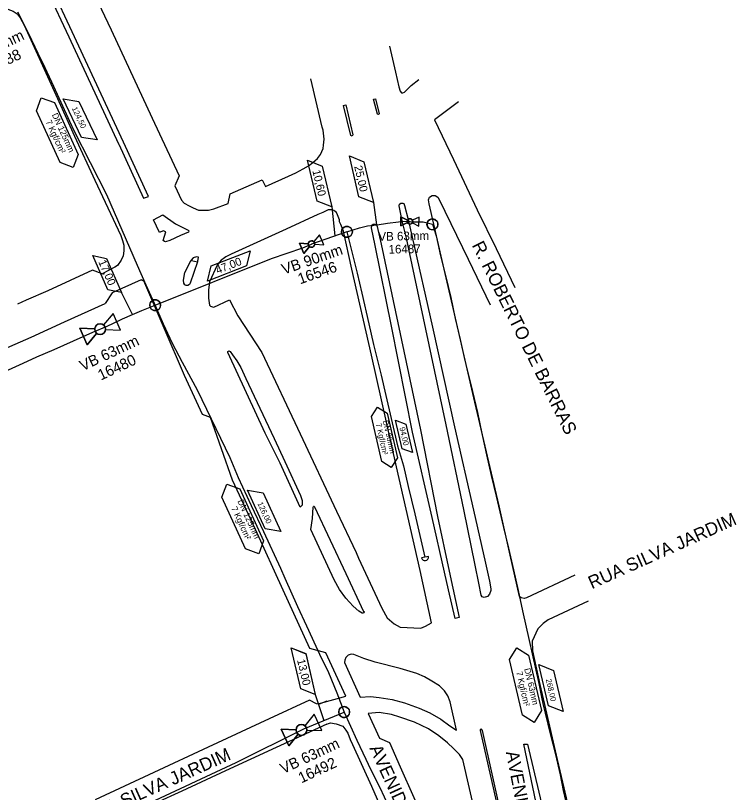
# Model space of a CAD drawing. Extents: x 656692 to 673945, y 7585994 to 7599066.
# Drawn here: x 669589.7 to 669990.1, y 7595459.1 to 7595890.6 of the extents above; entities that cross this region are included whole.
import ezdxf

# ---------------------------------------------------------------- set-up
doc = ezdxf.new("R2010")
doc.units = 0
for name, color, linetype in [('LOGRADOURO', 7, 'Continuous'), ('LOGRADOURO_TEXTO', 7, 'Continuous'), ('SIMBOLO', 7, 'Continuous'), ('TEXTO', 7, 'Continuous'), ('TUBO_PEAD_GN_125', 7, 'Continuous'), ('TUBO_PEAD_GN_63', 7, 'Continuous'), ('TUBO_PEAD_GN_90', 7, 'Continuous'), ('VALVULA_PEAD_63', 7, 'Continuous'), ('VALVULA_PEAD_90', 7, 'Continuous')]:
    doc.layers.add(name, color=color, linetype=linetype)

# ---------------------------------------------------------------- blocks, each defined once
blk = doc.blocks.new('VALVULA_PEAD_DN_17')
for points in [[(-0.0374, 0.0187), (-0.1395, 0.0698), (-0.1395, -0.0698), (-0.0374, -0.0187)], [(-0.0374, -0.0187), (-0.1395, -0.0698), (-0.1395, 0.0698), (-0.0374, 0.0187)], [(0.0374, -0.0187), (0.1395, -0.0698), (0.1395, 0.0698), (0.0374, 0.0187)], [(0.0374, -0.0187), (0.1395, -0.0698), (0.1395, 0.0698), (0.0374, 0.0187)]]:
    blk.add_lwpolyline(points)
blk.add_circle((0, 0), 0.0419)
for start, end in [(90, 270), (153.43495, 206.56505), (270, 90), (333.43495, 26.56505)]:
    blk.add_arc((0, 0), 0.0419, start, end)
blk = doc.blocks.new('VALVULA_PEAD_DN_16')
at = {"layer": 'VALVULA_PEAD_63'}
for points in [[(-0.0374, 0.0187), (-0.1395, 0.0698), (-0.1395, -0.0698), (-0.0374, -0.0187)], [(-0.0374, -0.0187), (-0.1395, -0.0698), (-0.1395, 0.0698), (-0.0374, 0.0187)], [(0.0374, -0.0187), (0.1395, -0.0698), (0.1395, 0.0698), (0.0374, 0.0187)], [(0.0374, -0.0187), (0.1395, -0.0698), (0.1395, 0.0698), (0.0374, 0.0187)]]:
    blk.add_lwpolyline(points, dxfattribs=at)
blk.add_circle((0, 0), 0.0419, dxfattribs=at)
for start, end in [(90, 270), (153.43495, 206.56505), (270, 90), (333.43495, 26.56505)]:
    blk.add_arc((0, 0), 0.0419, start, end, dxfattribs=at)
blk = doc.blocks.new('INTERLIGACAO_9')
at = {"layer": 'SIMBOLO'}
blk.add_circle((0, 0), 4.19, dxfattribs=at)
for start, end in [(0, 180), (180, 0)]:
    blk.add_arc((0, 0), 4.19, start, end, dxfattribs=at)

msp = doc.modelspace()

# ---------------------------------------------------------------- linework, layer by layer
at = {"layer": 'LOGRADOURO'}
for points in [[(669626.5, 7595917.1), (669642.76, 7595882.69), (669665.64, 7595833.62), (669680.49, 7595801.6), (669678.22, 7595796.05), (669681.86, 7595788.09), (669683.31, 7595786.42), (669686.12, 7595784.82), (669688.31, 7595783.67), (669691.24, 7595782.53), (669693.42, 7595782.38), (669696.76, 7595782.38), (669699.88, 7595783.14), (669707.82, 7595786.21), (669708.87, 7595791.5), (669726.73, 7595799.31), (669728.46, 7595795.59), (669741.37, 7595801.35), (669745.32, 7595803.18), (669749.49, 7595805.46), (669752.32, 7595807.01), (669754.83, 7595808.9), (669757.44, 7595811.23), (669759.07, 7595813.43), (669760.45, 7595816.65), (669760.81, 7595818.51), (669761.05, 7595821.97), (669760.86, 7595823.57), (669760.47, 7595826.84), (669760.05, 7595828.63), (669753.74, 7595855.33)], [(669553.79, 7595882.06), (669580.42, 7595893.61), (669582.82, 7595894.1), (669585.35, 7595894.02), (669588.34, 7595892.98), (669590.53, 7595891.47), (669592.25, 7595889.23), (669594.49, 7595885.22), (669611.97, 7595846.58), (669622.46, 7595823.54), (669633.74, 7595799.1), (669648.11, 7595768.42), (669649.11, 7595765.62), (669649.81, 7595762.99), (669649.9, 7595759.85), (669649.5, 7595757.16), (669648.42, 7595754.65), (669646.35, 7595751.78), (669644.89, 7595750.78), (669637.86, 7595747.18), (669632.34, 7595749.1), (669607.54, 7595737.68)], [(669797.31, 7595873.61), (669800.8, 7595859.03), (669802.64, 7595850.96), (669803.28, 7595848.52), (669804.09, 7595847.63), (669804.88, 7595847.67), (669805.68, 7595848.03), (669809.42, 7595851.65), (669813.63, 7595855.12)], [(669835.77, 7595842.7), (669822.33, 7595832.65), (669832.9, 7595810.63), (669846.14, 7595782.71), (669856.67, 7595761.12), (669867.05, 7595739.51)], [(669900.31, 7595579.73), (669873.55, 7595567.21), (669872.18, 7595566.8), (669870.6, 7595567.14), (669869.5, 7595567.96), (669864.44, 7595590.79), (669858.28, 7595618.33), (669844.74, 7595675.82), (669835.11, 7595717.66), (669826.58, 7595754.43), (669819.36, 7595786.07), (669819.1, 7595788.19), (669819.64, 7595789.73), (669821.1, 7595790.67), (669822.73, 7595790.7), (669824.28, 7595789.64), (669825.01, 7595788.42), (669841.04, 7595755.28), (669853.38, 7595729.85)], [(669690.68, 7595753.82), (669686.75, 7595741.96), (669686.28, 7595741.15), (669685.45, 7595740.68), (669684.49, 7595740.56), (669683.69, 7595741.09), (669683.23, 7595741.98), (669682.96, 7595743.57), (669683.71, 7595747.78), (669687.28, 7595754.63), (669687.33, 7595754.58), (669690.68, 7595753.82), (669691.15, 7595755.11), (669691.25, 7595756.29), (669690.21, 7595756.56), (669688.42, 7595756.04), (669687.28, 7595754.63)], [(669757.69, 7595508.22), (669773.04, 7595512.59), (669761.95, 7595536.58), (669753.17, 7595539.09), (669738.38, 7595571.37), (669722.99, 7595605.03), (669710.1, 7595632.55), (669697.93, 7595667.32), (669693.56, 7595668.97), (669683.56, 7595690.6), (669660.88, 7595743.27), (669659.5, 7595743.83), (669643.32, 7595736.53), (669639.47, 7595730.71)], [(669659.5, 7595743.83), (669660.88, 7595743.28), (669664.83, 7595734.55)], [(669607.54, 7595737.68), (669595.57, 7595732.41), (669590.79, 7595730.26)], [(669573.09, 7595444.9), (669568.9, 7595463.16), (669562.37, 7595492.14), (669557.21, 7595514.33), (669553.14, 7595532.15), (669552.15, 7595536.82), (669545.25, 7595567.44), (669541.15, 7595585.45), (669533.84, 7595617.5), (669528.2, 7595642.69), (669523.3, 7595663.52), (669518.93, 7595664.92), (669517.03, 7595673.72), (669516.85, 7595676.41), (669517.26, 7595678.43), (669518.23, 7595680.04), (669519, 7595680.94), (669535.25, 7595688.41), (669542.22, 7595686.89), (669552.84, 7595691.94), (669583.46, 7595705.45), (669598.26, 7595711.96), (669616.78, 7595720.51), (669639.47, 7595730.71)], [(669907.78, 7595565.23), (669885.57, 7595555.02), (669882.73, 7595552.97), (669879.76, 7595549.96), (669876.58, 7595543.18), (669876.74, 7595537.65), (669880.81, 7595518.96), (669884, 7595505.49), (669890.56, 7595477.33), (669899.18, 7595440.34), (669919.49, 7595352.19), (669922.93, 7595337.43), (669927.48, 7595318.19), (669928.82, 7595313.85), (669931.88, 7595309.53), (669937, 7595308.26), (669942.3, 7595308.75), (669944.73, 7595309.52), (669968, 7595320.27)], [(669762.51, 7595509.83), (669758.3, 7595508.19), (669756.76, 7595508.28), (669753, 7595510.3), (669730.61, 7595500.03), (669696.68, 7595484.27), (669666.46, 7595470.15), (669633.85, 7595455.06)], [(669845.58, 7595445.09), (669838.19, 7595477.44), (669836.22, 7595480.25), (669832.95, 7595483.5), (669829.58, 7595486.58), (669824.74, 7595490.52), (669818.97, 7595494.48), (669811.3, 7595498.16), (669803.15, 7595500.96), (669798.42, 7595502.35), (669791.71, 7595503.41), (669785.47, 7595502.94), (669791.84, 7595489.29), (669797.31, 7595486.82), (669803.34, 7595473.27), (669818.44, 7595439.25)], [(669652.94, 7595446.6), (669682.16, 7595460.01), (669706.4, 7595471.33), (669762.77, 7595497.12)], [(669761.52, 7595496.64), (669764.7, 7595497.67), (669767.78, 7595497.25), (669771.48, 7595495.84), (669773.04, 7595493.76), (669774.32, 7595491.97), (669775.54, 7595488.56), (669776.89, 7595485.73), (669787.41, 7595462.62), (669799.64, 7595434.65)], [(669860.86, 7595440.34), (669848.96, 7595493.48), (669848.48, 7595494.15), (669847.74, 7595493.99), (669847.68, 7595493.52), (669859.85, 7595440.29)], [(669884.68, 7595425.72), (669871.99, 7595485.94), (669874.02, 7595485.91), (669888.13, 7595426.35)]]:
    msp.add_lwpolyline(points, dxfattribs=at)
for points in [[(669607.45, 7595905.13), (669607.4, 7595904.23), (669607.57, 7595903.69), (669619.3, 7595878.82), (669646.8, 7595819.29), (669647.05, 7595819.15), (669660.73, 7595789.07), (669663.51, 7595790.14), (669649.55, 7595820.32), (669621.14, 7595881.57), (669610.2, 7595905.02)], [(669791.62, 7595836.01), (669791.25, 7595835.59), (669790.74, 7595835.69), (669788.42, 7595844.08), (669789.58, 7595844.3)], [(669777.01, 7595824.23), (669776.63, 7595823.5), (669775.97, 7595824), (669771.75, 7595840.54), (669773.11, 7595840.9)], [(669802.88, 7595785.84), (669803.72, 7595786.34), (669804.73, 7595786.34), (669805.3, 7595786.08), (669805.7, 7595785.06), (669807.73, 7595777.22), (669809.94, 7595767.5), (669821.24, 7595717.47), (669833.46, 7595662.21), (669844.08, 7595615.89), (669850.77, 7595586.39), (669852.97, 7595576.44), (669853.71, 7595572.18), (669853.64, 7595571.16), (669852.97, 7595569.18), (669851.77, 7595567.93), (669850.02, 7595567.35), (669848.78, 7595567.65), (669848.22, 7595568.72), (669846.94, 7595575.29), (669845.03, 7595585.29), (669838.61, 7595616.29), (669828.91, 7595663.3), (669817.63, 7595716.43), (669806.76, 7595766.85), (669804.51, 7595776.56), (669802.67, 7595784.92)], [(669678.43, 7595774.82), (669685.47, 7595771.42), (669685.92, 7595770.92), (669685.74, 7595770.27), (669681.28, 7595768.33), (669675.37, 7595765.69), (669672.96, 7595764.81), (669672.36, 7595765), (669671.7, 7595765.69), (669673.18, 7595770.45), (669671.67, 7595771.07), (669669.61, 7595770.13), (669666.29, 7595777.15), (669671.45, 7595779.9)], [(669799.94, 7595552.7), (669803.31, 7595550.91), (669814.86, 7595550.33), (669817.32, 7595551.47), (669820.76, 7595553.3), (669814.47, 7595582.37), (669801.31, 7595639.9), (669787.32, 7595701.9), (669776.43, 7595749.62), (669771.88, 7595770.79), (669770.34, 7595774.45), (669769.62, 7595776), (669769.6, 7595777.04), (669768.58, 7595779.96), (669767.89, 7595781.12), (669766.52, 7595782.27), (669765.49, 7595782.73), (669763.4, 7595782.57), (669761.89, 7595781.83), (669760.37, 7595781.2), (669757.52, 7595779.99), (669740.08, 7595771.96), (669709.4, 7595758.08), (669706.52, 7595756.62), (669704.98, 7595755.53), (669703.87, 7595754.64), (669701.61, 7595751.84), (669697.45, 7595742.58), (669696.84, 7595737.96), (669696.78, 7595733.6), (669697.45, 7595729.66), (669697.89, 7595729.2), (669699.1, 7595728.69), (669699.73, 7595728.65), (669708.43, 7595732.65), (669713.18, 7595723.87), (669726.55, 7595703.39), (669747.8, 7595658.31), (669768.03, 7595615.28), (669778.78, 7595592.33), (669780.18, 7595589.24), (669793.15, 7595561.4), (669796.02, 7595556.13)], [(669787.74, 7595774.35), (669788.39, 7595774.63), (669789.27, 7595774.65), (669790.12, 7595774.28), (669790.46, 7595773.4), (669792.74, 7595763.57), (669814.61, 7595660.4), (669824.08, 7595612.32), (669830.51, 7595582.05), (669836.06, 7595556.18), (669833.79, 7595555.75), (669830.13, 7595571.61), (669827.86, 7595581.43), (669821.05, 7595611.75), (669810.16, 7595659.17), (669798.56, 7595718.01), (669789.43, 7595762.92), (669787.34, 7595772.7)], [(669707.53, 7595703.78), (669707.67, 7595704.06), (669708.15, 7595704.26), (669708.83, 7595703.9), (669710.18, 7595702.21), (669712.57, 7595698.82), (669714.77, 7595695.15), (669717.59, 7595688.95), (669731.63, 7595659.26), (669733.26, 7595655.65), (669739.23, 7595642.82), (669748.03, 7595623.98), (669748.79, 7595621.15), (669748.87, 7595618.67), (669747.84, 7595617.51), (669736.58, 7595641.87), (669728.36, 7595658.56), (669707.63, 7595703.4)], [(669754.56, 7595611.23), (669755.03, 7595617.58), (669755.13, 7595617.95), (669755.31, 7595618.15), (669755.6, 7595618.09), (669755.81, 7595617.76), (669773.04, 7595580.76), (669783.02, 7595559.56), (669783.27, 7595559.51), (669783.22, 7595559.24), (669783.05, 7595558.87), (669782.65, 7595558.66), (669782.12, 7595558.74), (669780.31, 7595559.71), (669777.2, 7595562.6), (669773.13, 7595566.91), (669769.58, 7595571.8), (669766.65, 7595577.17), (669753.7, 7595605.08)], [(669825.08, 7595518.33), (669820.93, 7595520.87), (669816.86, 7595523.3), (669812.61, 7595525.14), (669803.37, 7595527.94), (669789.38, 7595531.4), (669783.13, 7595533.49), (669777.57, 7595535.79), (669776.09, 7595535.9), (669774.45, 7595535.4), (669773.17, 7595534.08), (669772.49, 7595532.59), (669772.34, 7595531.3), (669781.11, 7595512.06), (669786.75, 7595512.36), (669791.61, 7595511.85), (669798.81, 7595510.72), (669805.72, 7595508.86), (669813.79, 7595505.95), (669819.8, 7595503.27), (669825.96, 7595499.81), (669830.89, 7595496.17), (669834.56, 7595493.6), (669830.99, 7595509.36), (669829.84, 7595512.8), (669827.91, 7595515.53)]]:
    msp.add_lwpolyline(points, close=True, dxfattribs=at)
at = {"layer": 'SIMBOLO'}
for points in [[(669603.95, 7595844.94), (669611.22, 7595842.24), (669624.38, 7595813.46), (669621.67, 7595806.19), (669614.41, 7595808.9), (669601.25, 7595837.68), (669603.95, 7595844.94)], [(669790.8, 7595673.14), (669796.09, 7595669.8), (669801.74, 7595644.9), (669798.4, 7595639.61), (669793.11, 7595642.94), (669787.46, 7595667.85), (669790.8, 7595673.14)], [(669707.02, 7595630.36), (669714.29, 7595627.65), (669727.45, 7595598.87), (669724.74, 7595591.6), (669717.48, 7595594.31), (669704.31, 7595623.09), (669707.02, 7595630.36)], [(669868.05, 7595539.46), (669874.64, 7595535.38), (669881.87, 7595504.57), (669877.78, 7595497.98), (669871.19, 7595502.06), (669863.97, 7595532.87), (669868.05, 7595539.46)]]:
    msp.add_lwpolyline(points, dxfattribs=at)
at = {"layer": 'TEXTO'}
for p, q in [((669765.3, 7595784.29), (669766.96, 7595768.28)), ((669788.5, 7595786.68), (669790.16, 7595774.32)), ((669654.7, 7595724.55), (669648.46, 7595736.82)), ((669756.15, 7595513.55), (669760.98, 7595499.08))]:
    msp.add_line(p, q, dxfattribs=at)
for points in [[(669624.86, 7595842.77), (669634.98, 7595821.56), (669626.32, 7595822.91), (669616.14, 7595844.25), (669624.86, 7595842.77)], [(669760, 7595806.9), (669765.3, 7595784.29), (669757.23, 7595787.41), (669751.89, 7595810.17), (669760, 7595806.9)], [(669783.2, 7595809.29), (669788.5, 7595786.68), (669780.43, 7595789.8), (669775.09, 7595812.56), (669783.2, 7595809.29)], [(669640.2, 7595755.68), (669648.46, 7595736.82), (669640.92, 7595738.25), (669632.61, 7595757.23), (669640.2, 7595755.68)], [(669698.31, 7595751.49), (669719.93, 7595759.97), (669717.99, 7595751.53), (669696.24, 7595743), (669698.31, 7595751.49)], [(669698.31, 7595751.49), (669719.93, 7595759.97), (669718, 7595751.53), (669696.24, 7595743), (669698.31, 7595751.49)], [(669806.44, 7595663.64), (669810.15, 7595647.81), (669804.5, 7595649.99), (669800.76, 7595665.92), (669806.44, 7595663.64)], [(669727.23, 7595625.43), (669737.01, 7595604.05), (669728.37, 7595605.54), (669718.54, 7595627.05), (669727.23, 7595625.43)], [(669750.84, 7595536.17), (669756.14, 7595513.55), (669748.07, 7595516.68), (669742.73, 7595539.43), (669750.84, 7595536.17)], [(669750.84, 7595536.16), (669756.15, 7595513.55), (669748.07, 7595516.68), (669742.73, 7595539.43), (669750.84, 7595536.16)], [(669888.56, 7595526.88), (669893.93, 7595504), (669885.76, 7595507.16), (669880.36, 7595530.19), (669888.56, 7595526.88)]]:
    msp.add_lwpolyline(points, dxfattribs=at)
at = {"layer": 'TUBO_PEAD_GN_125'}
for points in [[(669590.7, 7595892.69), (669596.78, 7595880.52), (669602.1, 7595869.64), (669604.61, 7595864.4), (669609.59, 7595853.74), (669614.86, 7595842.37), (669619.65, 7595831.91), (669622.02, 7595826.67), (669640.27, 7595791.15), (669657.19, 7595751.87), (669662.12, 7595741.07), (669666.75, 7595730.79), (669671.67, 7595719.37), (669676.73, 7595708.66), (669682.14, 7595698.1), (669690.48, 7595682.61), (669700.88, 7595661.12), (669708.63, 7595645.08), (669713.24, 7595634.09), (669720.55, 7595618.52), (669727.45, 7595603.99), (669736.87, 7595583.56), (669739.33, 7595578.02), (669746.29, 7595562.3), (669751.19, 7595551.62), (669758.51, 7595535.92), (669763.56, 7595525.65), (669768.07, 7595514.48), (669772.18, 7595503.71)], [(669772.18, 7595503.71), (669779.22, 7595488.18), (669784.3, 7595477.64), (669786.74, 7595472.07), (669792.04, 7595461.75), (669794.34, 7595456.68), (669801.22, 7595441.08), (669806.29, 7595430.51), (669810.45, 7595420.39), (669814.54, 7595410.08), (669821.65, 7595392.3), (669828.01, 7595377.85), (669832.38, 7595367.25), (669839.26, 7595351.8), (669844.71, 7595340.75), (669852.94, 7595323.62), (669854.78, 7595319.98), (669858.93, 7595309.26), (669865.49, 7595292.74), (669869.6, 7595281.87), (669873.37, 7595271.9), (669876.69, 7595264.55)]]:
    msp.add_lwpolyline(points, dxfattribs=at)
at = {"layer": 'TUBO_PEAD_GN_63'}
for points in [[(669773.77, 7595770.45), (669780.74, 7595772.66), (669785.19, 7595773.69), (669790.6, 7595774.39), (669796.25, 7595775.3), (669802.39, 7595776.07), (669806.94, 7595776.32), (669810.8, 7595776.06), (669816.16, 7595776.06), (669821.29, 7595774.6)], [(669821.29, 7595774.6), (669823.24, 7595768.17), (669825.72, 7595757.06), (669828.7, 7595745.42), (669831.39, 7595733.99), (669833.87, 7595722.31), (669836.71, 7595710.61), (669839.21, 7595699), (669840.69, 7595693.06), (669843.54, 7595681.69), (669846.24, 7595670.02), (669848.73, 7595658.43), (669851.26, 7595646.6), (669853.94, 7595635.19), (669856.72, 7595623.71), (669860.76, 7595606.24), (669863.5, 7595594.75), (669866.24, 7595582.79), (669868.91, 7595571.23), (669871.29, 7595559.87), (669880.41, 7595519.58), (669881.75, 7595511.92), (669882.62, 7595508.41), (669886.71, 7595491.65), (669889.55, 7595480.21), (669892.12, 7595468.79), (669893.91, 7595460.26), (669896.29, 7595449.98)], [(669534.22, 7595671.46), (669540.46, 7595673.9), (669545.8, 7595675.99), (669555.57, 7595680.54), (669564.97, 7595684.69), (669573.21, 7595688.27), (669583.77, 7595692.82), (669593.9, 7595697.51), (669601.58, 7595701.04), (669611.21, 7595705.07), (669632.67, 7595714.76), (669640.62, 7595717.97), (669644.11, 7595719.62), (669649.04, 7595722.14), (669654.7, 7595724.55), (669659.88, 7595726.68), (669667.27, 7595729.71)], [(669593.23, 7595420.27), (669602.37, 7595424.36), (669635.18, 7595440.51), (669661.79, 7595452.21), (669712.19, 7595475.76), (669749.78, 7595494.45), (669772.18, 7595503.71)]]:
    msp.add_lwpolyline(points, dxfattribs=at)
at = {"layer": 'TUBO_PEAD_GN_90'}
for p, q in [((669773.77, 7595770.45), (669753.98, 7595763.58)), ((669818.98, 7595590.11), (669815.22, 7595589.36)), ((669818.98, 7595590.11), (669815.22, 7595589.36)), ((669818.98, 7595590.11), (669815.22, 7595589.36))]:
    msp.add_line(p, q, dxfattribs=at)
for points in [[(669773.77, 7595770.45), (669779.44, 7595747.53), (669781.95, 7595736.35), (669785.95, 7595719.4), (669788.49, 7595707.86), (669792.68, 7595690.88), (669795.34, 7595679.62), (669801.91, 7595651.67), (669805.14, 7595640.48), (669807.84, 7595629.01), (669811.38, 7595613.91), (669817.1, 7595589.74)], [(669667.27, 7595729.71), (669731.78, 7595755.6), (669749.26, 7595761.46), (669753.98, 7595763.58), (669753.98, 7595763.58)]]:
    msp.add_lwpolyline(points, dxfattribs=at)
msp.add_arc((669817.09, 7595589.77), 1.92, 192.5183, 10.2679, dxfattribs=at)
msp.add_arc((669817.09, 7595589.77), 1.92, 192.5183, 10.2679, dxfattribs=at)
msp.add_arc((669817.09, 7595589.77), 1.92, 192.5183, 10.2679, dxfattribs=at)

# ---------------------------------------------------------------- block references
at = {"layer": 'SIMBOLO', "xscale": 0.7229249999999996, "yscale": 0.7229249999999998, "rotation": 166.312122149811}
for p in [(669821.24, 7595774.58), (669773.73, 7595770.43), (669667.23, 7595729.69), (669772.18, 7595503.71)]:
    msp.add_blockref('INTERLIGACAO_9', p, dxfattribs=at)
at = {"layer": 'VALVULA_PEAD_63'}
for p, xscale, yscale, rotation in [((669808.75, 7595776.2), 36.14624999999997, 36.146249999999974, -0.8041979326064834), ((669636.65, 7595716.37), 72.29249999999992, 72.29249999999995, 23.827974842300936), ((669748.48, 7595493.8), 72.29249999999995, 72.29249999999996, 24.566402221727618)]:
    msp.add_blockref('VALVULA_PEAD_DN_16', p, dxfattribs=dict(at, xscale=xscale, yscale=yscale, rotation=rotation))
at = {"layer": 'VALVULA_PEAD_90', "xscale": 43.37549999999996, "yscale": 43.375499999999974, "rotation": 23.242767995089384}
msp.add_blockref('VALVULA_PEAD_DN_17', (669754.1, 7595763.66), dxfattribs=at)

# ---------------------------------------------------------------- texts
for s, height, rotation, p in [('VB 63mm', 6, 25.048, (669563.14, 7595862.61)), ('16588', 6, 25.048, (669573.23, 7595857.41)), ('VB 63mm', 4.8, 1.048, (669791.23, 7595765.44)), ('VB 90mm', 6, 19.0985, (669738.7, 7595746.59)), ('16487', 4.8, 1.048, (669796.91, 7595758.35)), ('16546', 6, 19.0985, (669747.69, 7595741.24)), ('VB 63mm', 6, 25.048, (669627, 7595693)), ('16480', 6, 25.048, (669637.09, 7595687.8)), ('VB 63mm', 6, 25.048, (669738.34, 7595469.27)), ('16492', 6, 25.048, (669748.42, 7595464.06))]:
    msp.add_text(s, height=height, rotation=rotation).set_placement(p)
at = {"layer": 'LOGRADOURO_TEXTO'}
for s, rotation, p in [('R. ROBERTO DE BARRAS', 296.3219, (669842.94, 7595763.03)), ('RUA SILVA JARDIM', 24.1047, (669909.76, 7595571.93)), ('RUA SILVA JARDIM', 24.1047, (669628.82, 7595441.33)), ('AVENIDA DOS ANDRADAS', 294.633, (669786.08, 7595483.65)), ('AVENIDA BARÃO DO RIO BRANCO', 280.9935, (669861.99, 7595481.46))]:
    msp.add_text(s, height=7.2, rotation=rotation, dxfattribs=at).set_placement(p)
at = {"layer": 'TEXTO'}
for s, height, rotation, p in [('124,50', 3.113, 295.4907, (669620.84, 7595838.99)), ('DN 125mm', 3.459, 294.5743, (669609.77, 7595835.45)), ('7 Kgf/cm²', 3.459, 294.5743, (669606.27, 7595831.56)), ('10,60', 4.447, 283.1976, (669754.51, 7595804.37)), ('25,00', 4.447, 283.1976, (669777.72, 7595806.75)), ('17,00', 4.447, 293.6346, (669635.54, 7595753.8)), ('47,00', 4.447, 21.4221, (669701.87, 7595746.89)), ('7 Kgf/cm²', 3.113, 282.775, (669789.73, 7595663.74)), ('DN 90mm', 3.113, 282.775, (669793.6, 7595665.36)), ('94,00', 3.113, 283.1976, (669802.89, 7595661.63)), ('DN 125mm', 3.459, 294.5743, (669712.83, 7595620.86)), ('126,00', 3.113, 294.5743, (669723.95, 7595619.58)), ('7 Kgf/cm²', 3.459, 294.5743, (669709.34, 7595616.98)), ('13,00', 4.447, 283.1976, (669746, 7595532.63)), ('7 Kgf/cm²', 3.459, 283.1976, (669867.69, 7595525.89)), ('DN 63mm', 3.459, 283.1976, (669872.19, 7595527.7)), ('268,00', 3.113, 283.1976, (669884.19, 7595521.8))]:
    msp.add_text(s, height=height, rotation=rotation, dxfattribs=at).set_placement(p)

doc.saveas('drawing.dxf')
